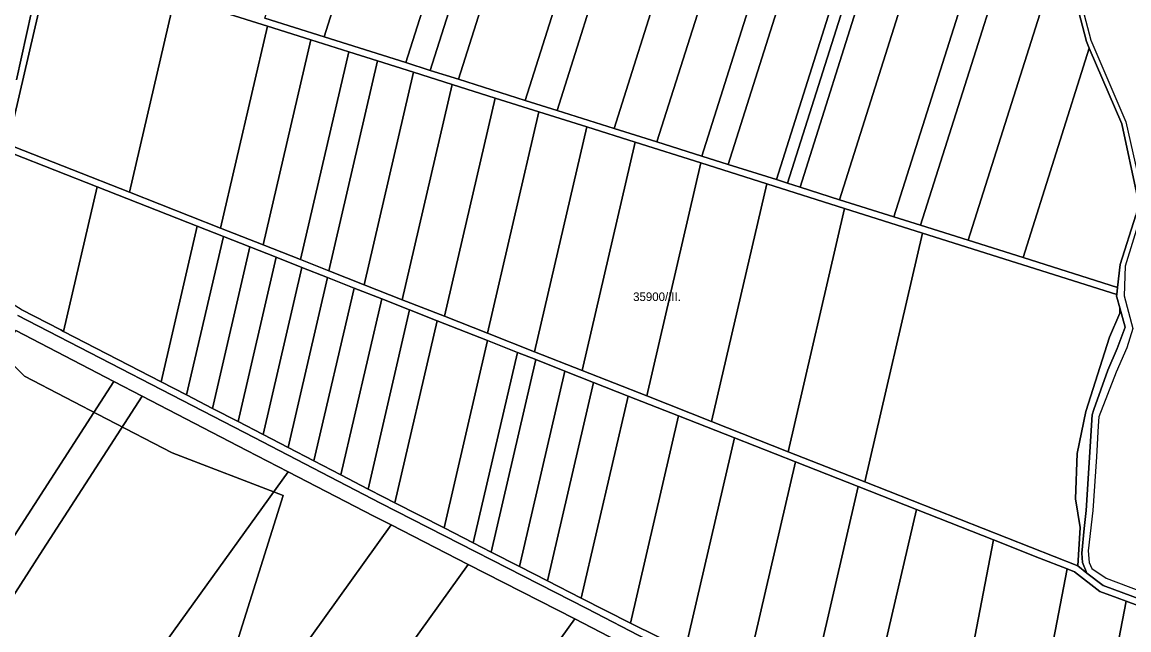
# Model space of a CAD drawing. Extents: x -545779 to -541342, y -1153413 to -1149956.
# Drawn here: x -542328 to -541682, y -1150888 to -1150533 of the extents above; entities that cross this region are included whole.
import ezdxf

# ---------------------------------------------------------------- set-up
doc = ezdxf.new("R2010")
doc.units = 0
for name, color, linetype in [('95560013', 7, 'Continuous'), ('95610013', 7, 'Continuous'), ('95630013', 7, 'Continuous'), ('95640013', 7, 'Continuous'), ('95660013', 7, 'Continuous')]:
    doc.layers.add(name, color=color, linetype=linetype)

msp = doc.modelspace()

# ---------------------------------------------------------------- linework, layer by layer
at = {"layer": '95560013'}
for points in [[(-542238.79, -1150518.76), (-542265.23, -1150632.79), (-542332.56, -1150606.25), (-542335.38, -1150600.88), (-542318.46, -1150527.93), (-542319.28, -1150493.32)], [(-542184.78, -1150535.83), (-542212.11, -1150653.73), (-542265.23, -1150632.79), (-542238.79, -1150518.76)], [(-542212.11, -1150653.73), (-542184.78, -1150535.83), (-542159.54, -1150543.81), (-542187.3, -1150663.52)], [(-542303.72, -1150714.04), (-542305.3, -1150713.22), (-542328.41, -1150701.27), (-542351.47, -1150687.05), (-542353.96, -1150681.05), (-542338.1, -1150612.62), (-542333.47, -1150610.19), (-542284.15, -1150629.63)], [(-542246.85, -1150743.47), (-542303.72, -1150714.04), (-542284.15, -1150629.63), (-542225.79, -1150652.64)], [(-542274.43, -1150743.21), (-542332.4, -1150833.13), (-542390.37, -1150923.05), (-542441.95, -1150897.24), (-542386.81, -1150805.35), (-542331.67, -1150713.45)], [(-542332.4, -1150833.13), (-542274.43, -1150743.21), (-542257.9, -1150751.81), (-542315.79, -1150841.6), (-542373.68, -1150931.4), (-542390.37, -1150923.05)], [(-542257.9, -1150751.81), (-542196.89, -1150783.53), (-542172.78, -1150796.01), (-542235.1, -1150882.79), (-542297.41, -1150969.57), (-542373.68, -1150931.4), (-542315.79, -1150841.6)], [(-542112.67, -1150827.06), (-542174.74, -1150913.48), (-542236.8, -1150999.9), (-542297.41, -1150969.57), (-542235.1, -1150882.79), (-542172.78, -1150796.01), (-542122.73, -1150821.92)], [(-542174.74, -1150913.48), (-542112.67, -1150827.06), (-542067.66, -1150850.1), (-542129.59, -1150936.33), (-542191.51, -1151022.56), (-542236.8, -1150999.9)], [(-541683.71, -1150871.59), (-541710.32, -1151009.63), (-541745.27, -1150993.23), (-541718.19, -1150852.74), (-541713.94, -1150854.41), (-541699.1, -1150865.91), (-541689.05, -1150869.62)], [(-541673.02, -1151027.14), (-541710.32, -1151009.63), (-541683.71, -1150871.59), (-541651.19, -1150883.61)], [(-542128.95, -1151053.86), (-542067.22, -1150967.9), (-542005.48, -1150881.94), (-541985.56, -1150892.13), (-542047.24, -1150978.01), (-542108.91, -1151063.89)]]:
    msp.add_lwpolyline(points, close=True, dxfattribs=at)
at = {"layer": '95610013'}
for points in [[(-542186.3, -1150531.15), (-542151.19, -1150420.07), (-542116.01, -1150308.76), (-542080.85, -1150317.68), (-542116.31, -1150429.88), (-542151.77, -1150542.07)], [(-542032.26, -1150330.01), (-542068.15, -1150443.58), (-542104.05, -1150557.15), (-542151.77, -1150542.07), (-542116.31, -1150429.88), (-542080.85, -1150317.68)], [(-542032.26, -1150330.01), (-542017.7, -1150333.71), (-542053.72, -1150447.69), (-542089.75, -1150561.67), (-542104.05, -1150557.15), (-542068.15, -1150443.58)], [(-542089.75, -1150561.67), (-542053.72, -1150447.69), (-542017.7, -1150333.71), (-542015.92, -1150334.16), (-542001.48, -1150339.61), (-542037.39, -1150453.24), (-542073.3, -1150566.86)], [(-542001.48, -1150339.61), (-541988.95, -1150344.33), (-541978.2, -1150354.11), (-541967.65, -1150367.96), (-542001.02, -1150473.56), (-542034.4, -1150579.16), (-542073.3, -1150566.86), (-542037.39, -1150453.24)], [(-542001.02, -1150473.56), (-541967.65, -1150367.96), (-541952.94, -1150386.19), (-541984.36, -1150485.61), (-542015.79, -1150585.04), (-542034.4, -1150579.16)], [(-541887.81, -1150625.44), (-541915.95, -1150616.6), (-541881.5, -1150507.58), (-541847.05, -1150398.57), (-541830.58, -1150384.47), (-541819.71, -1150379.22), (-541810.21, -1150379.92), (-541849.01, -1150502.68)], [(-541842.64, -1150505.21), (-541881.31, -1150627.55), (-541887.81, -1150625.44), (-541849.01, -1150502.68), (-541810.21, -1150379.92), (-541809.2, -1150379.99), (-541803.98, -1150382.9)], [(-541881.31, -1150627.55), (-541842.64, -1150505.21), (-541803.98, -1150382.9), (-541797.17, -1150386.69), (-541835.59, -1150508.27), (-541874.01, -1150629.85)], [(-541984.36, -1150485.61), (-541952.94, -1150386.19), (-541945.31, -1150395.64), (-541937.81, -1150401.27), (-541926.83, -1150408.59), (-541923.64, -1150409.27), (-541982.52, -1150595.56), (-542015.79, -1150585.04)], [(-541835.59, -1150508.27), (-541797.17, -1150386.69), (-541775.53, -1150398.53), (-541813.24, -1150517.84), (-541850.95, -1150637.15), (-541874.01, -1150629.85)], [(-541881.5, -1150507.58), (-541915.95, -1150616.6), (-541931.36, -1150611.73), (-541899.62, -1150511.28), (-541867.88, -1150410.84), (-541860.32, -1150410.81), (-541851.52, -1150402.4), (-541847.05, -1150398.57)], [(-541819.21, -1150647.18), (-541850.95, -1150637.15), (-541813.24, -1150517.84), (-541775.53, -1150398.53), (-541750.61, -1150411.86), (-541747.06, -1150418.91), (-541783.13, -1150533.04)], [(-541927.13, -1150507.21), (-541957.55, -1150603.45), (-541982.52, -1150595.56), (-541923.64, -1150409.27), (-541915.22, -1150411.06), (-541896.71, -1150410.97)], [(-541931.36, -1150611.73), (-541957.55, -1150603.45), (-541927.13, -1150507.21), (-541896.71, -1150410.97), (-541867.88, -1150410.84), (-541899.62, -1150511.28)], [(-541803.64, -1150652.09), (-541819.21, -1150647.18), (-541783.13, -1150533.04), (-541747.06, -1150418.91), (-541736.55, -1150439.82), (-541770.09, -1150545.94)], [(-541721.52, -1150488.78), (-541775.91, -1150660.86), (-541803.64, -1150652.09), (-541770.09, -1150545.94), (-541736.55, -1150439.82), (-541732.05, -1150448.75), (-541728.11, -1150456.58), (-541722.87, -1150473.65)], [(-541775.91, -1150660.86), (-541721.52, -1150488.78), (-541706.85, -1150544.85), (-541705.23, -1150548.62), (-541743.9, -1150670.98)], [(-542187.3, -1150663.52), (-542159.54, -1150543.81), (-542137.35, -1150550.83), (-542165.47, -1150672.12)], [(-541678.02, -1150646.12), (-541687.19, -1150674.93), (-541688.75, -1150688.41), (-541743.9, -1150670.98), (-541705.23, -1150548.62), (-541686.26, -1150592.85), (-541677.1, -1150635.63), (-541676.53, -1150638.29), (-541677.29, -1150642.27)], [(-542137.35, -1150550.83), (-542120.53, -1150556.14), (-542148.94, -1150678.64), (-542165.47, -1150672.12)], [(-542099.55, -1150562.77), (-542128.31, -1150686.77), (-542148.94, -1150678.64), (-542120.53, -1150556.14)], [(-542099.55, -1150562.77), (-542076.97, -1150569.91), (-542106.1, -1150695.53), (-542128.31, -1150686.77)], [(-542081.51, -1150705.22), (-542106.1, -1150695.53), (-542076.97, -1150569.91), (-542051.97, -1150577.81)], [(-542081.51, -1150705.22), (-542051.97, -1150577.81), (-542026.48, -1150585.86), (-542056.44, -1150715.1)], [(-541998.52, -1150594.7), (-542028.94, -1150725.94), (-542056.44, -1150715.1), (-542026.48, -1150585.86)], [(-541970.26, -1150603.63), (-542001.16, -1150736.89), (-542028.94, -1150725.94), (-541998.52, -1150594.7)], [(-541970.26, -1150603.63), (-541931.98, -1150615.73), (-541963.51, -1150751.73), (-542001.16, -1150736.89)], [(-541931.98, -1150615.73), (-541893.49, -1150627.9), (-541925.66, -1150766.65), (-541963.51, -1150751.73)], [(-541925.66, -1150766.65), (-541893.49, -1150627.9), (-541848.05, -1150642.24), (-541880.97, -1150784.27)], [(-541880.97, -1150784.27), (-541848.05, -1150642.24), (-541802.52, -1150656.65), (-541836.2, -1150801.91)], [(-542246.85, -1150743.47), (-542225.79, -1150652.64), (-542210.52, -1150658.66), (-542231.97, -1150751.17)], [(-542216.91, -1150758.96), (-542231.97, -1150751.17), (-542210.52, -1150658.66), (-542195.07, -1150664.75)], [(-541711.94, -1150850.9), (-541836.2, -1150801.91), (-541802.52, -1150656.65), (-541689.22, -1150692.46), (-541689.33, -1150693.39), (-541689.12, -1150694.15), (-541687.42, -1150700.33), (-541687.35, -1150703.33), (-541693.39, -1150717.33), (-541707.34, -1150760.81), (-541712.37, -1150785.34), (-541713.34, -1150811.71), (-541710.56, -1150828.57)], [(-542179.73, -1150670.79), (-542201.97, -1150766.68), (-542216.91, -1150758.96), (-542195.07, -1150664.75)], [(-542179.73, -1150670.79), (-542164.65, -1150676.74), (-542187.27, -1150774.3), (-542187.77, -1150774.04), (-542201.97, -1150766.68)], [(-542164.65, -1150676.74), (-542149.71, -1150682.63), (-542172.72, -1150781.85), (-542187.27, -1150774.3)], [(-542172.72, -1150781.85), (-542149.71, -1150682.63), (-542134.23, -1150688.73), (-542157.64, -1150789.67)], [(-542157.64, -1150789.67), (-542134.23, -1150688.73), (-542118.1, -1150695.09), (-542141.92, -1150797.83)], [(-542126.06, -1150806.06), (-542141.92, -1150797.83), (-542118.1, -1150695.09), (-542101.82, -1150701.51)], [(-542126.06, -1150806.06), (-542101.82, -1150701.51), (-542085.77, -1150707.83), (-542110.42, -1150814.13), (-542116.9, -1150810.81)], [(-542085.77, -1150707.83), (-542056.4, -1150719.41), (-542081.76, -1150828.79), (-542110.42, -1150814.13)], [(-542081.76, -1150828.79), (-542056.4, -1150719.41), (-542038.93, -1150726.3), (-542064.71, -1150837.51)], [(-542028.25, -1150730.51), (-542054.29, -1150842.84), (-542064.71, -1150837.51), (-542038.93, -1150726.3)], [(-542028.25, -1150730.51), (-542011.22, -1150737.23), (-542037.67, -1150851.33), (-542054.29, -1150842.84)], [(-542011.22, -1150737.23), (-541994.44, -1150743.86), (-542021.29, -1150859.71), (-542037.67, -1150851.33)], [(-541994.44, -1150743.86), (-541974.29, -1150751.78), (-542001.64, -1150869.77), (-542021.29, -1150859.71)], [(-541944.95, -1150763.35), (-541973.03, -1150884.45), (-542001.64, -1150869.77), (-541974.29, -1150751.78)], [(-541912.34, -1150776.2), (-541941.08, -1150900.17), (-541973.03, -1150884.45), (-541944.95, -1150763.35)], [(-541876.73, -1150790.24), (-541906.1, -1150916.94), (-541941.08, -1150900.17), (-541912.34, -1150776.2)], [(-541870.13, -1150934.18), (-541906.1, -1150916.94), (-541876.73, -1150790.24), (-541840.11, -1150804.68)], [(-541840.11, -1150804.68), (-541806.1, -1150818.08), (-541836.74, -1150950.19), (-541870.13, -1150934.18)], [(-541787.65, -1150973.34), (-541825.54, -1150955.56), (-541836.74, -1150950.19), (-541806.1, -1150818.08), (-541761.14, -1150835.81)], [(-541734.34, -1150846.37), (-541718.19, -1150852.74), (-541745.27, -1150993.23), (-541787.65, -1150973.34), (-541761.14, -1150835.81)], [(-542067.22, -1150967.9), (-542128.95, -1151053.86), (-542191.51, -1151022.56), (-542129.59, -1150936.33), (-542067.66, -1150850.1), (-542005.48, -1150881.94)]]:
    msp.add_lwpolyline(points, close=True, dxfattribs=at)
at = {"layer": '95630013'}
for points in [[(-541677.1, -1150635.63), (-541686.26, -1150592.85), (-541705.23, -1150548.62), (-541706.85, -1150544.85), (-541721.52, -1150488.78)], [(-541714.17, -1150506.12), (-541704.27, -1150544.01), (-541683.98, -1150591.73), (-541673.47, -1150638.23)], [(-542322.47, -1150527.52), (-542331.21, -1150567.12)], [(-541646.75, -1150881.02), (-541697.14, -1150862.37), (-541706.72, -1150855.22), (-541709.28, -1150848.94), (-541709.66, -1150843.58), (-541708.17, -1150829.2), (-541707.08, -1150818.67), (-541703.62, -1150762.82), (-541702.51, -1150759.64), (-541694.49, -1150736.66), (-541689, -1150724.04), (-541684.34, -1150711.48), (-541687.42, -1150700.33), (-541689.12, -1150694.15), (-541689.33, -1150693.39), (-541689.22, -1150692.46), (-541688.75, -1150688.41), (-541687.19, -1150674.93), (-541678.02, -1150646.12)], [(-541675.28, -1150647.01), (-541684.35, -1150675.91), (-541684.91, -1150693.21), (-541679.89, -1150712.34), (-541683.37, -1150723.57), (-541689.59, -1150737.85), (-541699.62, -1150763.88), (-541699.96, -1150769.23), (-541701.1, -1150787.3), (-541703.08, -1150818.57), (-541705.94, -1150842.11), (-541705.28, -1150849.04), (-541703.75, -1150852.54), (-541695.38, -1150858.04), (-541646.63, -1150876.57)], [(-542330.38, -1150704.75), (-542192.55, -1150776.06), (-542118.73, -1150814.37), (-541998.47, -1150875.88), (-541963.17, -1150894.02), (-541827.25, -1150959.17), (-541673.46, -1151031.35)], [(-541677.17, -1151039.39), (-541687.38, -1151034.5), (-541710.82, -1151023.16), (-541740.3, -1151008.9), (-541751.35, -1151003.55), (-541778.54, -1150990.41), (-541848.73, -1150956.79), (-541864.34, -1150949.52), (-541950.17, -1150909.55), (-541965.98, -1150902.18), (-541966.13, -1150902.11), (-541974.07, -1150898.02), (-541985.56, -1150892.13), (-542005.48, -1150881.94), (-542067.66, -1150850.1), (-542112.67, -1150827.06), (-542122.73, -1150821.92), (-542172.78, -1150796.01), (-542196.89, -1150783.53), (-542257.9, -1150751.81), (-542274.43, -1150743.21), (-542331.67, -1150713.45)]]:
    msp.add_lwpolyline(points, dxfattribs=at)
at = {"layer": '95640013'}
for points in [[(-542186.3, -1150531.15), (-542151.77, -1150542.07), (-542104.05, -1150557.15), (-542089.75, -1150561.67), (-542073.3, -1150566.86), (-542034.4, -1150579.16), (-542015.79, -1150585.04), (-541982.52, -1150595.56), (-541957.55, -1150603.45), (-541931.36, -1150611.73), (-541915.95, -1150616.6), (-541887.81, -1150625.44), (-541881.31, -1150627.55), (-541874.01, -1150629.85), (-541850.95, -1150637.15), (-541819.21, -1150647.18), (-541803.64, -1150652.09), (-541775.91, -1150660.86), (-541743.9, -1150670.98), (-541688.75, -1150688.41), (-541689.22, -1150692.46), (-541802.52, -1150656.65), (-541848.05, -1150642.24), (-541893.49, -1150627.9), (-541931.98, -1150615.73), (-541970.26, -1150603.63), (-541998.52, -1150594.7), (-542026.48, -1150585.86), (-542051.97, -1150577.81), (-542076.97, -1150569.91), (-542099.55, -1150562.77), (-542120.53, -1150556.14), (-542137.35, -1150550.83), (-542159.54, -1150543.81), (-542184.78, -1150535.83), (-542238.79, -1150518.76)], [(-542318.46, -1150527.93), (-542335.38, -1150600.88)], [(-542331.21, -1150567.12), (-542322.47, -1150527.52)], [(-542332.56, -1150606.25), (-542265.23, -1150632.79), (-542212.11, -1150653.73), (-542187.3, -1150663.52), (-542165.47, -1150672.12), (-542148.94, -1150678.64), (-542128.31, -1150686.77), (-542106.1, -1150695.53), (-542081.51, -1150705.22), (-542056.44, -1150715.1), (-542028.94, -1150725.94), (-542001.16, -1150736.89), (-541963.51, -1150751.73), (-541925.66, -1150766.65), (-541880.97, -1150784.27), (-541836.2, -1150801.91), (-541711.94, -1150850.9), (-541706.72, -1150855.22), (-541697.14, -1150862.37), (-541646.75, -1150881.02)], [(-541651.19, -1150883.61), (-541683.71, -1150871.59), (-541689.05, -1150869.62), (-541699.1, -1150865.91), (-541713.94, -1150854.41), (-541718.19, -1150852.74), (-541734.34, -1150846.37), (-541761.14, -1150835.81), (-541806.1, -1150818.08), (-541840.11, -1150804.68), (-541876.73, -1150790.24), (-541912.34, -1150776.2), (-541944.95, -1150763.35), (-541974.29, -1150751.78), (-541994.44, -1150743.86), (-542011.22, -1150737.23), (-542028.25, -1150730.51), (-542038.93, -1150726.3), (-542056.4, -1150719.41), (-542085.77, -1150707.83), (-542101.82, -1150701.51), (-542118.1, -1150695.09), (-542134.23, -1150688.73), (-542149.71, -1150682.63), (-542164.65, -1150676.74), (-542179.73, -1150670.79), (-542195.07, -1150664.75), (-542210.52, -1150658.66), (-542225.79, -1150652.64), (-542284.15, -1150629.63), (-542333.47, -1150610.19)], [(-541673.46, -1151031.35), (-541827.25, -1150959.17), (-541963.17, -1150894.02), (-541998.47, -1150875.88), (-542118.73, -1150814.37), (-542192.55, -1150776.06), (-542330.38, -1150704.75)], [(-542328.41, -1150701.27), (-542305.3, -1150713.22), (-542303.72, -1150714.04), (-542246.85, -1150743.47), (-542231.97, -1150751.17), (-542216.91, -1150758.96), (-542201.97, -1150766.68), (-542187.77, -1150774.04), (-542187.27, -1150774.3), (-542172.72, -1150781.85), (-542157.64, -1150789.67), (-542141.92, -1150797.83), (-542126.06, -1150806.06), (-542116.9, -1150810.81), (-542110.42, -1150814.13), (-542081.76, -1150828.79), (-542064.71, -1150837.51), (-542054.29, -1150842.84), (-542037.67, -1150851.33), (-542021.29, -1150859.71), (-542001.64, -1150869.77), (-541973.03, -1150884.45), (-541941.08, -1150900.17)]]:
    msp.add_lwpolyline(points, dxfattribs=at)
msp.add_lwpolyline([(-541684.34, -1150711.48), (-541689, -1150724.04), (-541694.49, -1150736.66), (-541702.51, -1150759.64), (-541703.62, -1150762.82), (-541707.08, -1150818.67), (-541708.17, -1150829.2), (-541709.66, -1150843.58), (-541709.28, -1150848.94), (-541706.72, -1150855.22), (-541711.94, -1150850.9), (-541710.56, -1150828.57), (-541713.34, -1150811.71), (-541712.37, -1150785.34), (-541707.34, -1150760.81), (-541693.39, -1150717.33), (-541687.35, -1150703.33), (-541687.42, -1150700.33)], close=True, dxfattribs=at)
at = {"layer": '95660013'}
for points in [[(-541714.17, -1150506.12), (-541704.27, -1150544.01), (-541683.98, -1150591.73), (-541673.47, -1150638.23)], [(-541675.28, -1150647.01), (-541684.35, -1150675.91), (-541684.91, -1150693.21), (-541679.89, -1150712.34), (-541683.37, -1150723.57), (-541689.59, -1150737.85), (-541699.62, -1150763.88), (-541699.96, -1150769.23), (-541701.1, -1150787.3), (-541703.08, -1150818.57), (-541705.94, -1150842.11), (-541705.28, -1150849.04), (-541703.75, -1150852.54), (-541695.38, -1150858.04), (-541646.63, -1150876.57)], [(-542367.768, -1150699.113), (-542326.618, -1150740.263), (-542278.77, -1150765.144), (-542240.419, -1150784.849), (-542175.693, -1150809.905), (-542213.276, -1150929.962), (-542166.296, -1150951.885), (-542082.778, -1150986.336), (-542055.636, -1150993.644), (-542041.02, -1150998.864), (-542022.228, -1151021.831), (-541989.866, -1151033.315), (-541948.107, -1151056.282), (-541943.93, -1151064.634), (-541934.535, -1151094.909), (-541919.919, -1151116.311), (-541892.776, -1151153.894), (-541881.292, -1151182.081), (-541882.335, -1151223.84)], [(-541882.335, -1151223.84), (-541881.292, -1151182.081), (-541892.776, -1151153.894), (-541919.919, -1151116.311), (-541934.535, -1151094.909), (-541943.93, -1151064.634), (-541948.107, -1151056.282), (-541989.866, -1151033.315), (-542022.228, -1151021.831), (-542041.02, -1150998.864), (-542055.636, -1150993.644), (-542082.778, -1150986.336), (-542166.296, -1150951.885), (-542213.276, -1150929.962), (-542175.693, -1150809.905), (-542240.419, -1150784.849), (-542278.77, -1150765.144), (-542326.618, -1150740.263), (-542367.768, -1150699.113)]]:
    msp.add_lwpolyline(points, dxfattribs=at)

# ---------------------------------------------------------------- texts
msp.add_text('35900/III.', height=5, rotation=0, dxfattribs=at).set_placement((-541971.41, -1150696.294))

doc.saveas('drawing.dxf')
